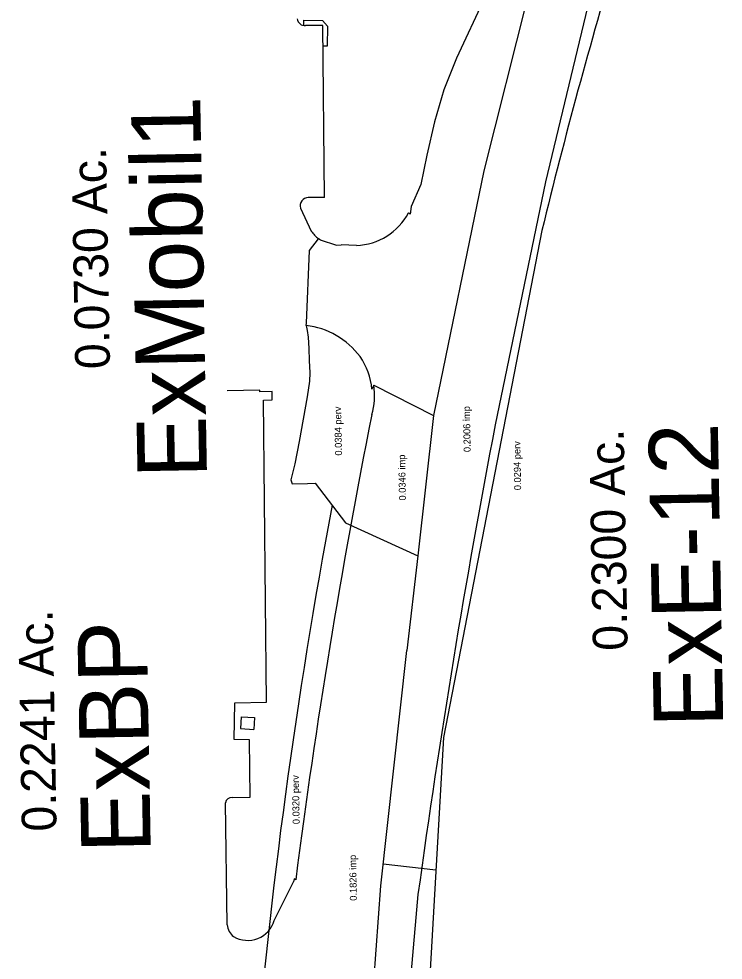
# Model space of a CAD drawing. Extents: x 925564 to 926134, y 853260 to 858402.
# Drawn here: x 925642.7 to 925926.7, y 857548.1 to 857927.7 of the extents above; entities that cross this region are included whole.
import ezdxf

# ---------------------------------------------------------------- set-up
doc = ezdxf.new("R2010")
doc.units = 0
for name, color, linetype in [('DrainDivides01', 7, 'Continuous'), ('PavtMisc_ep', 7, 'Continuous'), ('TextLabel', 7, 'Continuous')]:
    doc.layers.add(name, color=color, linetype=linetype)

msp = doc.modelspace()

# ---------------------------------------------------------------- linework, layer by layer
at = {"layer": 'DrainDivides01'}
for p, q in [((925859.1, 857981.28), (925830.19, 857866.43)), ((925765.31, 857925.1), (925758.37, 857925.04)), ((925765.94, 857855.73), (925765.31, 857925.1)), ((925830.19, 857866.43), (925809.98, 857767.73)), ((925765.94, 857855.73), (925759.41, 857855.63)), ((925756.26, 857851.38), (925760.63, 857842.14)), ((925853.64, 857842.36), (925813.91, 857637.85)), ((925758.53, 857804.06), (925758.92, 857802.02)), ((925785.83, 857779.96), (925785.09, 857778.32)), ((925785.83, 857779.96), (925809.98, 857767.73)), ((925809.98, 857767.73), (925803.55, 857711.1)), ((925803.55, 857711.1), (925799.21, 857672.96)), ((925788.69, 857577.98), (925799.21, 857672.96)), ((925813.91, 857637.85), (925804.32, 857470.39)), ((925789.67, 857586.89), (925810.86, 857584.51)), ((925780.72, 857471.45), (925788.69, 857577.98))]:
    msp.add_line(p, q, dxfattribs=at)
for points in [[(925758.53, 857804.06), (925758.76, 857805.01), (925759.94, 857834.23), (925763.57, 857839.02)], [(925758.92, 857802.02), (925759.43, 857799.38), (925759.64, 857794.75), (925759.81, 857789.87), (925759.99, 857785), (925759.91, 857781.53), (925758.97, 857775.28), (925757.33, 857766.26), (925755.69, 857757.25), (925754.05, 857748.23), (925752.42, 857741.75), (925752.88, 857740.13), (925759.08, 857740.35), (925762.19, 857740.46), (925774.42, 857724.47), (925803.55, 857711.1)]]:
    msp.add_lwpolyline(points, dxfattribs=at)
for centre, radius, start, end in [((927874.19, 857352.82), 2079, 163.16294, 166.38054), ((928061.19, 857302.51), 2332, 169.3984, 175.20115)]:
    msp.add_arc(centre, radius, start, end, dxfattribs=at)
for centre, major_axis, ratio, start_param, end_param in [((925758.02, 857928.09), (0.25, 3.05), 0.999852, 1.768601, 3.337477), ((925759.52, 857852.26), (2.54, 2.22), 0.999812, 0.886224, 2.688141), ((925771.29, 857849.22), (8.55, -9.57), 0.996718, 4.570122, 4.906004), ((925754.79, 857772.41), (25.79, 18.73), 0.999904, 0.014774, 0.82481), ((925758.08, 857776.02), (-16.08, 21.88), 0.997729, 4.164682, 4.687894)]:
    msp.add_ellipse(centre, major_axis=major_axis, ratio=ratio, start_param=start_param, end_param=end_param, dxfattribs=at)
at = {"layer": 'PavtMisc_ep'}
for p, q in [((925877.86, 857957.08), (925855.06, 857861.93)), ((925832.05, 857939.32), (925819.14, 857911.81)), ((925757.47, 857927.2), (925757.43, 857925.08)), ((925757.47, 857927.2), (925765.19, 857927.08)), ((925765.19, 857927.08), (925767.12, 857924.82)), ((925767.12, 857924.82), (925767.08, 857916.69)), ((925767.08, 857916.69), (925765.38, 857916.73)), ((925819.14, 857911.81), (925814.12, 857899.08)), ((925814.12, 857899.08), (925810.33, 857886.22)), ((925810.33, 857886.22), (925807.24, 857872.73)), ((925807.24, 857872.73), (925804.87, 857860.9)), ((925855.06, 857861.93), (925834.79, 857763.94)), ((925804.87, 857860.9), (925800.95, 857852.04)), ((925800.95, 857852.04), (925800.58, 857848.96)), ((925800.58, 857848.96), (925799.83, 857849.47)), ((925764.21, 857838.56), (925763.57, 857839.02)), ((925764.21, 857838.56), (925770.85, 857836.41)), ((925770.85, 857836.41), (925772.68, 857836.57)), ((925778.87, 857836.37), (925772.68, 857836.57)), ((925729.48, 857637), (925729.87, 857651.84)), ((925729.87, 857651.84), (925742.57, 857652.12)), ((925732.34, 857646.2), (925732.05, 857641.47)), ((925732.34, 857646.2), (925737.78, 857645.89)), ((925737.78, 857645.89), (925737.49, 857641.16)), ((925732.05, 857641.47), (925737.49, 857641.16)), ((925735.74, 857636.86), (925729.48, 857637)), ((925735.98, 857613.75), (925735.74, 857636.86)), ((925726.75, 857562.32), (925726.04, 857611.56)), ((925728.71, 857613.67), (925735.98, 857613.75)), ((925753.7, 857580.81), (925753.43, 857579.68)), ((925754.37, 857580.49), (925753.7, 857580.81)), ((925745.69, 857564.07), (925753.43, 857579.68))]:
    msp.add_line(p, q, dxfattribs=at)
msp.add_lwpolyline([(925742.57, 857652.12), (925741.35, 857773.98), (925744.89, 857774.04), (925744.83, 857777.43), (925739.86, 857777.34), (925739.85, 857777.96), (925726.77, 857777.73)], dxfattribs=at)
for centre, major_axis, ratio, start_param, end_param in [((925777.98, 857861.1), (-18.74, -16.18), 0.999592, 0.89473, 1.939864), ((925757.79, 857775.88), (-27.32, -7.55), 0.99973, 2.593427, 3.016476), ((928442.95, 857236.42), (412.75, 2717.67), 0.98605, 1.524747, 1.593914), ((929359.24, 857085.97), (-384.29, -3583.32), 0.995865, 4.629528, 4.682797), ((925728.44, 857611.27), (-0.19, -2.41), 0.999013, 3.105349, 4.670999), ((928603.71, 857303.24), (33.77, -2818.01), 0.998185, 4.604015, 4.674208), ((925733.32, 857562.76), (-4.75, -4.55), 0.999456, 5.586524, 6.430304), ((925734.95, 857567.23), (1.09, -11.15), 0.999459, 5.655326, 7.470461)]:
    msp.add_ellipse(centre, major_axis=major_axis, ratio=ratio, start_param=start_param, end_param=end_param, dxfattribs=at)

# ---------------------------------------------------------------- texts
at = {"layer": 'TextLabel'}
for s, height, p in [('ExMobil1', 28, (925718.59, 857742.69)), ('0.0730 Ac.', 14, (925679.47, 857786.57)), ('0.0384 perv', 2.8, (925773.02, 857751.59)), ('0.2006 imp', 2.8, (925824.92, 857753.01)), ('ExE-12', 28, (925926.79, 857642.19)), ('0.2300 Ac.', 14, (925888.23, 857672.97)), ('0.0294 perv', 2.8, (925845.27, 857737.63)), ('0.0346 imp', 2.8, (925798.8, 857733.47)), ('0.2241 Ac.', 14, (925657.94, 857600.05)), ('ExBP', 28, (925695.92, 857591.49)), ('0.0320 perv', 2.8, (925755.95, 857602.93)), ('0.1826 imp', 2.8, (925779.01, 857572.04))]:
    msp.add_text(s, height=height, rotation=91.0261, dxfattribs=at).set_placement(p)

doc.saveas('drawing.dxf')
